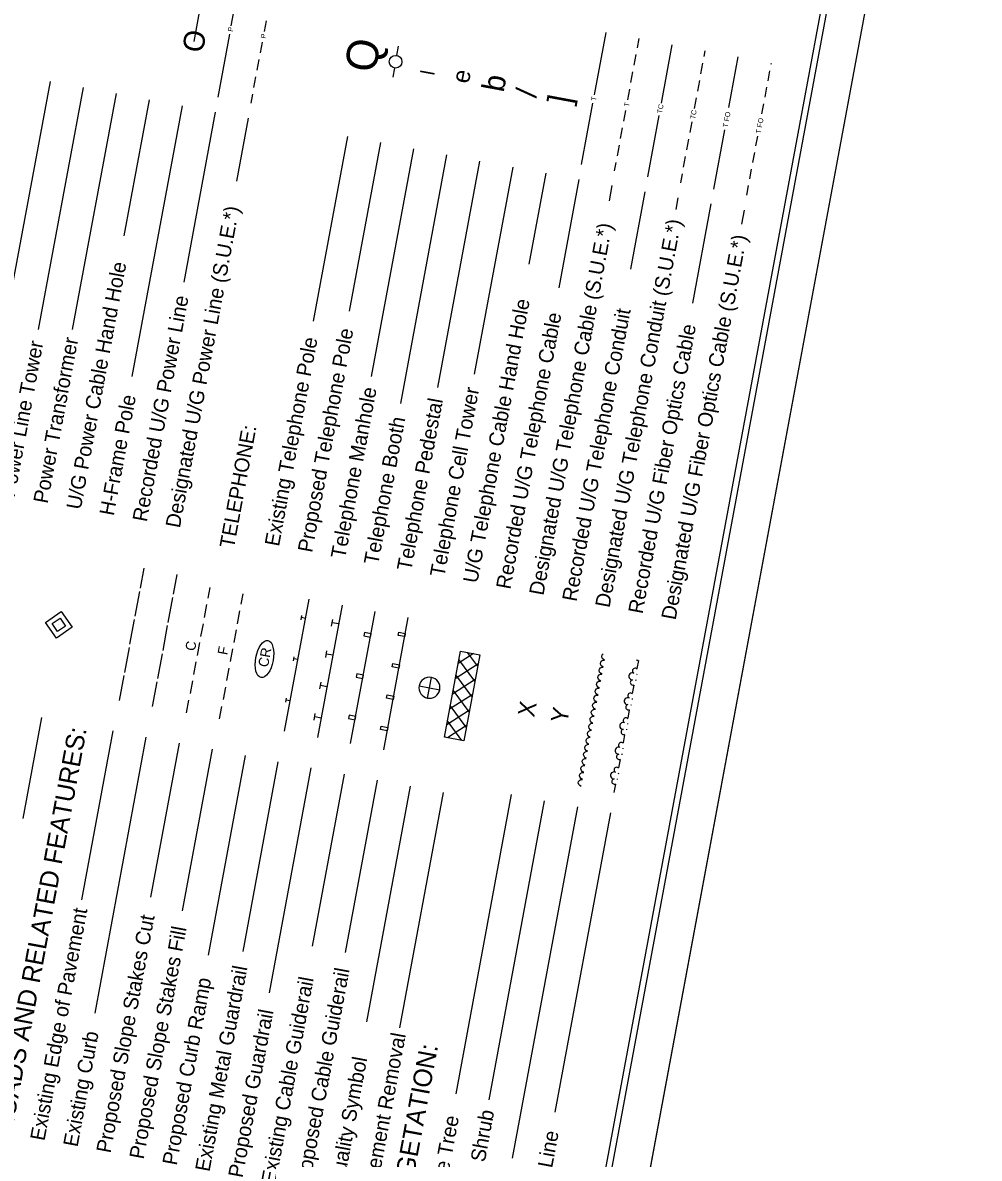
# Model space of a CAD drawing. Extents: x 1665923 to 1668724, y 690926 to 694920.
# Drawn here: x 1667823 to 1668393, y 691534 to 692210 of the extents above; entities that cross this region are included whole.
import ezdxf

# ---------------------------------------------------------------- set-up
doc = ezdxf.new("R2010")
doc.units = 0
for name, color, linetype in [('Prop ROW Permanent Easement CELL', 7, 'Continuous'), ('Prop WCC CELL', 7, 'Continuous'), ('Sheet Cutting Line CELL', 7, 'Continuous'), ('Sheet Plot Border Inside CELL', 7, 'Continuous'), ('Sheet Plot Border Outside CELL', 7, 'Continuous'), ('Sheet Symbology CELL', 7, 'Continuous')]:
    doc.layers.add(name, color=color, linetype=linetype)

msp = doc.modelspace()

# ---------------------------------------------------------------- linework, layer by layer
at = {"layer": 'Prop ROW Permanent Easement CELL'}
msp.add_line((1667844.85, 691851.15), (1667844.85, 691851.15), dxfattribs=at)
for points in [[(1667836.93, 691852.62), (1667846.32, 691859.07), (1667852.77, 691849.68), (1667843.38, 691843.23)], [(1667840.89, 691851.89), (1667845.59, 691855.11), (1667848.81, 691850.42), (1667844.12, 691847.19)]]:
    msp.add_lwpolyline(points, close=True, dxfattribs=at)
at = {"layer": 'Prop WCC CELL'}
msp.add_ellipse((1667967.21, 691830.8), major_axis=(2.05, 11.03), ratio=0.462467, dxfattribs=at)
at = {"layer": 'Sheet Cutting Line CELL'}
msp.add_line((1668085.16, 690926.11), (1668392.51, 692581.83), dxfattribs=at)
at = {"layer": 'Sheet Plot Border Inside CELL'}
msp.add_lwpolyline([(1668065.46, 690942.99), (1668369.62, 692581.5), (1667332.24, 692774.07), (1667028.08, 691135.56)], close=True, dxfattribs=at)
at = {"layer": 'Sheet Plot Border Outside CELL'}
msp.add_lwpolyline([(1668085.16, 690926.11), (1668392.51, 692581.83), (1667310.99, 692782.59), (1667003.64, 691126.87)], close=True, dxfattribs=at)
at = {"layer": 'Sheet Symbology CELL'}
for p, q in [((1667947.43, 692207.67), (1667954.17, 692243.97)), ((1667925.38, 692198.46), (1667929.03, 692218.12)), ((1667967.15, 692204.33), (1667968.34, 692210.72)), ((1667939.57, 692165.31), (1667946.52, 692202.76)), ((1668163.56, 692166.58), (1668170.47, 692203.81)), ((1668189.12, 692194.68), (1668190.13, 692200.16)), ((1667964.8, 692191.65), (1667965.98, 692198.04)), ((1668045.89, 692190.11), (1668046.92, 692195.64)), ((1668203.34, 692161.7), (1668209.8, 692196.51)), ((1668228.84, 692189.51), (1668229.46, 692192.86)), ((1667962.88, 692181.32), (1667964.07, 692187.72)), ((1668187.2, 692184.36), (1668188.39, 692190.75)), ((1668226.92, 692179.19), (1668228.11, 692185.58)), ((1668243.54, 692159.1), (1668249.13, 692189.21)), ((1668268.67, 692184.91), (1668268.79, 692185.56)), ((1668044.52, 692182.74), (1668043.49, 692177.21)), ((1668185.28, 692174.04), (1668186.47, 692180.43)), ((1668266.85, 692175.08), (1668267.94, 692180.98)), ((1667839.6, 692174.7), (1667810.67, 692018.86)), ((1667960.96, 692171), (1667962.15, 692177.39)), ((1668225.01, 692168.86), (1668226.19, 692175.25)), ((1667859.26, 692171.05), (1667832.53, 692027.01)), ((1667878.93, 692167.4), (1667852.85, 692026.9)), ((1667959.23, 692161.66), (1667960.23, 692167.07)), ((1668183.37, 692163.71), (1668184.55, 692170.1)), ((1668223.09, 692158.54), (1668224.28, 692164.93)), ((1668265.02, 692165.25), (1668266.12, 692171.15)), ((1667898.59, 692163.75), (1667883.57, 692082.81)), ((1667918.26, 692160.1), (1667888.34, 691998.95)), ((1668155.87, 692125.16), (1668162.65, 692161.66)), ((1668263.19, 692155.42), (1668264.29, 692161.32)), ((1667937.92, 692156.45), (1667919.13, 692055.22)), ((1667957.58, 692152.8), (1667950.61, 692115.23)), ((1668181.01, 692151.03), (1668182.2, 692157.42)), ((1668195.2, 692117.86), (1668201.97, 692154.32)), ((1668179.1, 692140.71), (1668180.28, 692147.1)), ((1668220.44, 692144.28), (1668221.63, 692150.67)), ((1668234.53, 692110.56), (1668241.07, 692145.83)), ((1668016.58, 692141.85), (1667996.16, 692031.84)), ((1668036.24, 692138.2), (1668017.61, 692037.85)), ((1668218.53, 692133.96), (1668219.71, 692140.35)), ((1668259.64, 692136.24), (1668260.73, 692142.14)), ((1668055.9, 692134.55), (1668030.74, 691999)), ((1668075.57, 692130.9), (1668048.1, 691982.93)), ((1668177.18, 692130.38), (1668178.37, 692136.77)), ((1668257.81, 692126.41), (1668258.91, 692132.31)), ((1668095.23, 692127.25), (1668070.2, 691992.39)), ((1668175.53, 692121.51), (1668176.45, 692126.45)), ((1668216.61, 692123.63), (1668217.8, 692130.03)), ((1668114.9, 692123.6), (1668092.04, 692000.48)), ((1668134.56, 692119.95), (1668124.52, 692065.83)), ((1668214.86, 692114.21), (1668215.88, 692119.7)), ((1668255.99, 692116.58), (1668257.08, 692122.48)), ((1668154.22, 692116.3), (1668142.26, 692051.84)), ((1668173.89, 692112.65), (1668172.22, 692103.66)), ((1668254.19, 692106.91), (1668255.26, 692112.65)), ((1668193.55, 692109), (1668184.99, 692062.86)), ((1668213.22, 692105.35), (1668211.93, 692098.4)), ((1668232.88, 692101.7), (1668221.93, 692042.68)), ((1668252.55, 692098.05), (1668250.98, 692089.63)), ((1667893.39, 691873.02), (1667895.58, 691884.81)), ((1667913.05, 691869.36), (1667915.24, 691881.16)), ((1667890.29, 691856.3), (1667893.02, 691871.05)), ((1667909.95, 691852.65), (1667912.69, 691867.4)), ((1667934.62, 691873.35), (1667933.45, 691867.05)), ((1667954.28, 691869.7), (1667953.11, 691863.4)), ((1667932.74, 691863.22), (1667931.3, 691855.5)), ((1667979.15, 691787.77), (1667993.75, 691866.43)), ((1668013.42, 691862.78), (1667998.82, 691784.12)), ((1667887.18, 691839.59), (1667889.92, 691854.33)), ((1667952.4, 691859.57), (1667950.97, 691851.85)), ((1667988.95, 691854.24), (1667989.4, 691856.7)), ((1667991.63, 691855.01), (1667989.18, 691855.47)), ((1668007.11, 691850.45), (1668007.84, 691854.38)), ((1668018.48, 691780.47), (1668033.08, 691859.13)), ((1668038.14, 691776.82), (1668052.74, 691855.48)), ((1667906.85, 691835.94), (1667909.58, 691850.68)), ((1667930.63, 691851.86), (1667929.21, 691844.24)), ((1667950.29, 691848.21), (1667948.88, 691840.59)), ((1668011.36, 691851.69), (1668007.48, 691852.42)), ((1667928.54, 691840.61), (1667927.12, 691832.94)), ((1667884.08, 691822.87), (1667886.82, 691837.62)), ((1667903.74, 691819.22), (1667906.48, 691833.97)), ((1667948.2, 691836.96), (1667946.78, 691829.29)), ((1668003.64, 691831.77), (1668004.37, 691835.7)), ((1668007.89, 691833.01), (1668004.01, 691833.73)), ((1668074.25, 691784.31), (1668083.76, 691835.53)), ((1668091.58, 691834.08), (1668082.4, 691828.21)), ((1668083.76, 691835.53), (1668095.27, 691833.4)), ((1668095.27, 691833.4), (1668085.76, 691782.17)), ((1668094.02, 691826.66), (1668088.09, 691834.73)), ((1668167.89, 691832.28), (1668168.06, 691833.21)), ((1668168.06, 691833.21), (1668168.7, 691833.9)), ((1668168.7, 691833.9), (1668168.76, 691833.94)), ((1667926.39, 691829.05), (1667925.01, 691821.58)), ((1667984.38, 691829.66), (1667984.84, 691832.12)), ((1667987.07, 691830.43), (1667984.61, 691830.89)), ((1668094.23, 691827.79), (1668080.71, 691819.07)), ((1668092.33, 691817.57), (1668082.82, 691830.47)), ((1668167.11, 691828.1), (1668167.29, 691829.03)), ((1668167.41, 691827.23), (1668167.11, 691828.1)), ((1668167.29, 691829.03), (1668167.92, 691829.73)), ((1668167.94, 691826.52), (1668167.41, 691827.23)), ((1668168.18, 691831.41), (1668167.89, 691832.28)), ((1668167.92, 691829.73), (1668168.66, 691830.15)), ((1668168.82, 691826.05), (1668167.94, 691826.52)), ((1668168.71, 691830.7), (1668168.18, 691831.41)), ((1668168.66, 691830.15), (1668169.54, 691830.19)), ((1668169.59, 691830.23), (1668168.71, 691830.7)), ((1668188.98, 691825.1), (1668189.9, 691830.02)), ((1667880.98, 691806.16), (1667883.72, 691820.91)), ((1667946.06, 691825.4), (1667944.67, 691817.93)), ((1668065.34, 691813.7), (1668066.49, 691819.85)), ((1668090.63, 691808.42), (1668081.13, 691821.38)), ((1668165.56, 691819.74), (1668165.73, 691820.67)), ((1668165.86, 691818.87), (1668165.56, 691819.74)), ((1668165.73, 691820.67), (1668166.37, 691821.37)), ((1668166.34, 691823.92), (1668166.51, 691824.85)), ((1668166.63, 691823.05), (1668166.34, 691823.92)), ((1668166.37, 691821.37), (1668167.11, 691821.79)), ((1668166.51, 691824.85), (1668167.15, 691825.55)), ((1668167.16, 691822.34), (1668166.63, 691823.05)), ((1668167.11, 691821.79), (1668167.98, 691821.83)), ((1668167.15, 691825.55), (1668167.89, 691825.97)), ((1668168.04, 691821.87), (1668167.16, 691822.34)), ((1668167.89, 691825.97), (1668168.76, 691826.01)), ((1668188.83, 691821.52), (1668188.92, 691822.01)), ((1667900.64, 691802.51), (1667903.38, 691817.26)), ((1667924.3, 691817.75), (1667922.92, 691810.32)), ((1667943.96, 691814.1), (1667942.58, 691806.67)), ((1668000.17, 691813.09), (1668000.9, 691817.02)), ((1668004.42, 691814.33), (1668000.54, 691815.05)), ((1668059.2, 691814.84), (1668065.34, 691813.7)), ((1668064.2, 691807.56), (1668065.34, 691813.7)), ((1668065.34, 691813.7), (1668071.49, 691812.56)), ((1668092.53, 691818.65), (1668079.02, 691809.97)), ((1668164.18, 691812.32), (1668164.82, 691813.01)), ((1668164.79, 691815.56), (1668164.96, 691816.49)), ((1668165.08, 691814.69), (1668164.79, 691815.56)), ((1668164.82, 691813.01), (1668165.56, 691813.43)), ((1668164.96, 691816.49), (1668165.6, 691817.19)), ((1668165.61, 691813.98), (1668165.08, 691814.69)), ((1668165.56, 691813.43), (1668166.43, 691813.48)), ((1668165.6, 691817.19), (1668166.34, 691817.61)), ((1668166.49, 691813.52), (1668165.61, 691813.98)), ((1668166.39, 691818.16), (1668165.86, 691818.87)), ((1668166.34, 691817.61), (1668167.21, 691817.65)), ((1668167.27, 691817.69), (1668166.39, 691818.16)), ((1668186.25, 691810.36), (1668187.16, 691815.27)), ((1668188.19, 691818.08), (1668188.28, 691818.57)), ((1667920.77, 691798.77), (1667922.16, 691806.24)), ((1667979.82, 691805.08), (1667980.28, 691807.54)), ((1667982.51, 691805.85), (1667980.05, 691806.31)), ((1668090.83, 691809.51), (1668077.33, 691800.88)), ((1668088.93, 691799.28), (1668079.45, 691812.28)), ((1668163.23, 691807.2), (1668163.41, 691808.14)), ((1668163.53, 691806.33), (1668163.23, 691807.2)), ((1668163.41, 691808.14), (1668164.04, 691808.83)), ((1668164.06, 691805.63), (1668163.53, 691806.33)), ((1668164.01, 691811.38), (1668164.18, 691812.32)), ((1668164.31, 691810.51), (1668164.01, 691811.38)), ((1668164.04, 691808.83), (1668164.78, 691809.26)), ((1668164.84, 691809.8), (1668164.31, 691810.51)), ((1668164.78, 691809.26), (1668165.66, 691809.3)), ((1668165.71, 691809.34), (1668164.84, 691809.8)), ((1668186.09, 691806.77), (1668186.18, 691807.27)), ((1667940.44, 691795.12), (1667941.82, 691802.59)), ((1668089.14, 691800.41), (1668075.63, 691791.73)), ((1668087.25, 691790.19), (1668077.75, 691803.14)), ((1668161.68, 691798.85), (1668161.86, 691799.78)), ((1668161.86, 691799.78), (1668162.49, 691800.48)), ((1668162.46, 691803.02), (1668162.63, 691803.96)), ((1668162.75, 691802.16), (1668162.46, 691803.02)), ((1668162.49, 691800.48), (1668163.23, 691800.9)), ((1668162.63, 691803.96), (1668163.27, 691804.65)), ((1668163.28, 691801.45), (1668162.75, 691802.16)), ((1668163.23, 691800.9), (1668164.11, 691800.94)), ((1668163.27, 691804.65), (1668164.01, 691805.08)), ((1668164.16, 691800.98), (1668163.28, 691801.45)), ((1668164.01, 691805.08), (1668164.88, 691805.12)), ((1668164.94, 691805.16), (1668164.06, 691805.63)), ((1668183.51, 691795.61), (1668184.42, 691800.52)), ((1668185.45, 691803.33), (1668185.54, 691803.83)), ((1667834.6, 691795.92), (1667823.46, 691735.93)), ((1667996.71, 691794.41), (1667997.44, 691798.34)), ((1668000.96, 691795.65), (1667997.07, 691796.37)), ((1668084.63, 691782.38), (1668076.05, 691793.99)), ((1668160.91, 691794.67), (1668161.08, 691795.6)), ((1668161.2, 691793.8), (1668160.91, 691794.67)), ((1668161.08, 691795.6), (1668161.72, 691796.3)), ((1668161.73, 691793.09), (1668161.2, 691793.8)), ((1668161.98, 691797.98), (1668161.68, 691798.85)), ((1668161.72, 691796.3), (1668162.46, 691796.72)), ((1668162.61, 691792.62), (1668161.73, 691793.09)), ((1668162.51, 691797.27), (1668161.98, 691797.98)), ((1668162.46, 691796.72), (1668163.33, 691796.76)), ((1668163.39, 691796.8), (1668162.51, 691797.27)), ((1667877.03, 691788.04), (1667858.35, 691687.41)), ((1668087.45, 691791.27), (1668076.02, 691783.98)), ((1668159.36, 691786.31), (1668159.53, 691787.24)), ((1668159.65, 691785.44), (1668159.36, 691786.31)), ((1668159.53, 691787.24), (1668160.17, 691787.94)), ((1668160.13, 691790.49), (1668160.3, 691791.42)), ((1668160.43, 691789.62), (1668160.13, 691790.49)), ((1668160.17, 691787.94), (1668160.91, 691788.36)), ((1668160.3, 691791.42), (1668160.94, 691792.12)), ((1668160.96, 691788.91), (1668160.43, 691789.62)), ((1668160.91, 691788.36), (1668161.78, 691788.4)), ((1668160.94, 691792.12), (1668161.68, 691792.54)), ((1668161.84, 691788.44), (1668160.96, 691788.91)), ((1668161.68, 691792.54), (1668162.55, 691792.58)), ((1668182.71, 691788.59), (1668182.8, 691789.08)), ((1668183.35, 691792.03), (1668183.44, 691792.52)), ((1667896.69, 691784.39), (1667866.19, 691620.05)), ((1667916.36, 691780.74), (1667899.35, 691689.12)), ((1668085.76, 691782.17), (1668074.25, 691784.31)), ((1668074.84, 691784.2), (1668074.35, 691784.85)), ((1668157.98, 691778.89), (1668158.62, 691779.58)), ((1668158.58, 691782.13), (1668158.75, 691783.07)), ((1668158.88, 691781.26), (1668158.58, 691782.13)), ((1668158.62, 691779.58), (1668159.35, 691780)), ((1668158.75, 691783.07), (1668159.39, 691783.76)), ((1668159.41, 691780.55), (1668158.88, 691781.26)), ((1668159.35, 691780), (1668160.23, 691780.05)), ((1668159.39, 691783.76), (1668160.13, 691784.18)), ((1668160.29, 691780.09), (1668159.41, 691780.55)), ((1668160.18, 691784.73), (1668159.65, 691785.44)), ((1668160.13, 691784.18), (1668161, 691784.22)), ((1668161.06, 691784.26), (1668160.18, 691784.73)), ((1668180.77, 691780.86), (1668181.68, 691785.78)), ((1667936.02, 691777.09), (1667918.18, 691681)), ((1667955.69, 691773.44), (1667933.62, 691654.55)), ((1668157.03, 691773.77), (1668157.2, 691774.71)), ((1668157.33, 691772.91), (1668157.03, 691773.77)), ((1668157.2, 691774.71), (1668157.84, 691775.4)), ((1668157.85, 691772.2), (1668157.33, 691772.91)), ((1668157.8, 691777.95), (1668157.98, 691778.89)), ((1668158.1, 691777.08), (1668157.8, 691777.95)), ((1668157.84, 691775.4), (1668158.58, 691775.83)), ((1668158.63, 691776.38), (1668158.1, 691777.08)), ((1668158.58, 691775.83), (1668159.45, 691775.87)), ((1668159.51, 691775.91), (1668158.63, 691776.38)), ((1668179.98, 691773.84), (1668180.07, 691774.33)), ((1668180.61, 691777.28), (1668180.71, 691777.77)), ((1667975.2, 691769.66), (1667954.25, 691656.75)), ((1667994.87, 691766.01), (1667970, 691632.06)), ((1668155.48, 691765.42), (1668155.65, 691766.35)), ((1668155.65, 691766.35), (1668156.29, 691767.05)), ((1668156.25, 691769.6), (1668156.43, 691770.53)), ((1668156.55, 691768.73), (1668156.25, 691769.6)), ((1668156.29, 691767.05), (1668157.03, 691767.47)), ((1668156.43, 691770.53), (1668157.06, 691771.23)), ((1668157.08, 691768.02), (1668156.55, 691768.73)), ((1668157.03, 691767.47), (1668157.9, 691767.51)), ((1668157.06, 691771.23), (1668157.8, 691771.65)), ((1668157.96, 691767.55), (1668157.08, 691768.02)), ((1668157.8, 691771.65), (1668158.68, 691771.69)), ((1668158.73, 691771.73), (1668157.85, 691772.2)), ((1668178.03, 691766.11), (1668178.95, 691771.03)), ((1668014.53, 691762.36), (1667995.5, 691659.81)), ((1668154.7, 691761.24), (1668154.88, 691762.17)), ((1668155, 691760.37), (1668154.7, 691761.24)), ((1668154.74, 691758.69), (1668155.48, 691759.11)), ((1668154.88, 691762.17), (1668155.51, 691762.87)), ((1668155.53, 691759.66), (1668155, 691760.37)), ((1668155.77, 691764.55), (1668155.48, 691765.42)), ((1668155.48, 691759.11), (1668156.35, 691759.15)), ((1668155.51, 691762.87), (1668156.25, 691763.29)), ((1668156.41, 691759.19), (1668155.53, 691759.66)), ((1668156.3, 691763.84), (1668155.77, 691764.55)), ((1668156.25, 691763.29), (1668157.12, 691763.33)), ((1668157.18, 691763.37), (1668156.3, 691763.84)), ((1668177.24, 691759.09), (1668177.33, 691759.58)), ((1668177.88, 691762.53), (1668177.97, 691763.02)), ((1668034.2, 691758.71), (1668015.16, 691656.16)), ((1668053.86, 691755.06), (1668027.83, 691614.83)), ((1668153.93, 691757.06), (1668154.1, 691757.99)), ((1668154.22, 691756.19), (1668153.93, 691757.06)), ((1668154.1, 691757.99), (1668154.74, 691758.69)), ((1668154.75, 691755.48), (1668154.22, 691756.19)), ((1668155.63, 691755.01), (1668154.75, 691755.48)), ((1668175.3, 691751.36), (1668176.21, 691756.28)), ((1668073.52, 691751.41), (1668047.49, 691611.18)), ((1668114.04, 691750.13), (1668080.98, 691572.05)), ((1668133.71, 691746.48), (1668100.65, 691568.4)), ((1668153.37, 691742.83), (1668114.55, 691533.72)), ((1668173.03, 691739.18), (1668139.98, 691561.1))]:
    msp.add_line(p, q, dxfattribs=at)
for points in [[(1667332.46, 692761.31), (1667058.7, 691286.51), (1668090.06, 691095.06), (1668363.83, 692569.86)], [(1668046.71, 691844.87), (1668047.07, 691846.83), (1668051, 691846.1), (1668050.64, 691844.14)], [(1668030.25, 691843.87), (1668030.61, 691845.83), (1668026.68, 691846.56), (1668026.31, 691844.6)], [(1668043.24, 691826.19), (1668043.6, 691828.15), (1668047.54, 691827.42), (1668047.17, 691825.46)], [(1668025.68, 691819.29), (1668026.05, 691821.25), (1668022.12, 691821.98), (1668021.75, 691820.02)], [(1668039.77, 691807.5), (1668040.14, 691809.47), (1668044.07, 691808.74), (1668043.7, 691806.77)], [(1668021.12, 691794.71), (1668021.49, 691796.67), (1668017.55, 691797.4), (1668017.19, 691795.44)], [(1668036.3, 691788.82), (1668036.67, 691790.79), (1668040.6, 691790.06), (1668040.24, 691788.09)]]:
    msp.add_lwpolyline(points, close=True, dxfattribs=at)
msp.add_circle((1668045.19, 692186.39), 3.75, dxfattribs=at)
for centre, radius, start, end in [((1668189.16, 691831.63), 1.58, 235.73497, 283.23294), ((1668065.35, 691813.7), 6.25, 79.47834, 169.48288), ((1668065.35, 691813.7), 6.25, 349.47834, 79.48288), ((1668186.08, 691820.5), 2.06, 65.44771, 273.5202), ((1668187.7, 691823.76), 1.58, 40.25243, 241.049), ((1668065.35, 691813.7), 6.25, 169.47834, 259.48288), ((1668186.42, 691816.88), 1.58, 97.9189, 298.71547), ((1668065.35, 691813.7), 6.25, 259.47834, 349.48288), ((1668183.34, 691805.76), 2.06, 65.44771, 273.5202), ((1668184.96, 691809.02), 1.58, 40.25243, 241.049), ((1668183.69, 691802.13), 1.58, 97.9189, 298.71547), ((1668180.6, 691791.01), 2.06, 65.44771, 273.5202), ((1668182.23, 691794.27), 1.58, 40.25243, 241.049), ((1668180.95, 691787.38), 1.58, 97.9189, 298.71547), ((1668179.49, 691779.52), 1.58, 40.25243, 241.049), ((1668177.87, 691776.26), 2.06, 65.44771, 273.5202), ((1668178.21, 691772.64), 1.58, 97.9189, 298.71547), ((1668176.75, 691764.77), 1.58, 40.25243, 241.049), ((1668175.13, 691761.52), 2.06, 65.44771, 273.5202), ((1668175.47, 691757.89), 1.58, 97.9189, 298.71547)]:
    msp.add_arc(centre, radius, start, end, dxfattribs=at)

# ---------------------------------------------------------------- texts
at = {"layer": 'Prop WCC CELL'}
msp.add_text('CR', height=6, rotation=79.48395, dxfattribs=at).set_placement((1667969.26, 691825.62))
at = {"layer": 'Sheet Symbology CELL'}
for s, height, p in [('P', 3, (1667948.28, 692204.06)), ('O', 12.5, (1667930.38, 692191.17)), ('P', 3, (1667967.88, 692200.03)), ('Q', 18.75, (1668033.03, 692179.11)), ('l', 8.25, (1668068.15, 692177.93)), ('e', 10.5, (1668088.72, 692172.97)), ('b', 13.2, (1668109.46, 692167.74)), ('/', 12.5, (1668128.85, 692164.5)), (']', 13.5, (1668148.91, 692160.27)), ('T', 3, (1668164.4, 692162.91)), ('T', 3, (1668184.09, 692159.36)), ('TC', 3, (1668203.69, 692155.38)), ('TC', 3, (1668223.4, 692151.97)), ('T FO', 3, (1668242.82, 692147.03)), ('T FO', 3, (1668262.48, 692143.34)), ('Designated U/G Power Line (S.U.E.*)', 8.75, (1667916.83, 691908.43)), ('Designated U/G Telephone Conduit (S.U.E.*)', 8.75, (1668172.47, 691860.98)), ('Designated U/G Telephone Cable (S.U.E.*)', 8.75, (1668133.14, 691868.28)), ('Designated U/G Fiber Optics Cable (S.U.E.*)', 8.75, (1668211.8, 691853.68)), ('U/G Power Cable Hand Hole', 8.75, (1667857.84, 691919.37)), ('Recorded U/G Power Line', 8.75, (1667897.17, 691912.07)), ('U/G Telephone Cable Hand Hole', 8.75, (1668093.81, 691875.58)), ('Recorded U/G Telephone Cable', 8.75, (1668113.48, 691871.93)), ('Recorded U/G Telephone Conduit', 8.75, (1668152.81, 691864.63)), ('Recorded U/G Fiber Optics Cable', 8.75, (1668192.13, 691857.33)), ('Power Transformer', 8.75, (1667838.16, 691923)), ('Proposed Telephone Pole', 8.75, (1667995.49, 691893.82)), ('Power Line Tower', 8.75, (1667818.5, 691926.66)), ('Existing Telephone Pole', 8.75, (1667975.83, 691897.47)), ('Telephone Manhole', 8.75, (1668015.16, 691890.17)), ('Telephone Cell Tower', 8.75, (1668074.15, 691879.23)), ('H-Frame Pole', 8.75, (1667877.51, 691915.72)), ('Telephone Pedestal', 8.75, (1668054.48, 691882.87)), ('TELEPHONE:', 8.75, (1667948.99, 691896.29)), ('Telephone Booth', 8.75, (1668034.82, 691886.52)), ('C', 5.93, (1667925.78, 691835.27)), ('F', 5.93, (1667945.05, 691832.91)), ('X', 10, (1668127.61, 691795.81)), ('Y', 10, (1668147.27, 691792.16)), ('ROADS AND RELATED FEATURES:', 11, (1667816.62, 691547.27)), ('Existing Edge of Pavement', 8.75, (1667836.29, 691543.62)), ('Proposed Slope Stakes Cut', 8.75, (1667875.62, 691536.32)), ('Proposed Slope Stakes Fill', 8.75, (1667895.28, 691532.67)), ('Existing Metal Guardrail', 8.75, (1667934.46, 691525.24)), ('Proposed Cable Guiderail', 8.75, (1667993.44, 691514.31)), ('Proposed Curb Ramp', 8.75, (1667914.94, 691529.02)), ('Existing Cable Guiderail', 8.75, (1667973.78, 691517.96)), ('Proposed Guardrail', 8.75, (1667954.12, 691521.61)), ('Existing Curb', 8.75, (1667855.95, 691539.97)), ('Pavement Removal', 8.75, (1668032.77, 691507)), ('VEGETATION:', 11, (1668052.51, 691503.33)), ('Equality Symbol', 8.75, (1668013.11, 691510.65)), ('Single Tree', 8.75, (1668072.1, 691499.41)), ('Single Shrub', 8.75, (1668091.77, 691495.76)), ('Woods Line', 8.75, (1668131.1, 691488.46))]:
    msp.add_text(s, height=height, rotation=79.48395, dxfattribs=at).set_placement(p)

doc.saveas('drawing.dxf')
